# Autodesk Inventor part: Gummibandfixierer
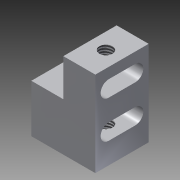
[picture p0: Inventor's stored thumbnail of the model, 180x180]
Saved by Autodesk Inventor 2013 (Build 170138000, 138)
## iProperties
Created: 2012-08
Part Number: Gummibandfixierer
Material: Aluminium 6061
Document SubType Name: Modeling
Designer: rYan
Mass: 2.85346 g
Surface Area: 11.8121 cm^2
Volume: 1.05294 cm^3
Density: 2.71 g/cm^3
Author: rYan
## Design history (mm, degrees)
sketch "Skizze1"
  geometry: L1 (0, 0)-(0, 16); L2 (0, 16)-(6, 16); L3 (6, 16)-(6, 9); L4 (6, 9)-(12, 9); L5 (12, 9)-(12, 0); L6 (12, 0)-(0, 0)
  constraints: 12 end point, 4 parallel, 1 perpendicular, 1 vertical
  dimensions: "d2" = 6 distance of L1.end L2.end; "d3" = 6 distance of L3.end L4.end; "d4" = 9 distance of L4.end L5.end; "d12" = 7 distance between parallel lines of L4 L2
extrude "Extrusion1" new body sketch "Skizze1" stored distance "d5" = 10; taper "d6" = 0 deg
sketch "Skizze2"
  geometry: L1 (9, 10)-(9, 0) reference; L2 (0, 10)-(0, 0) reference; L3 (4, 7.5)-(4, 2.5); L4 (7, 7.5)-(7, 2.5); L5 (0, 5)-(9, 5); A1 r 1.5 centre (5.5, 7.5) between (7, 7.5) and (4, 7.5); A2 r 1.5 centre (5.5, 2.5) between (4, 2.5) and (7, 2.5)
  constraints: 6 end point, 4 point on circle, 4 tangent, 2 centre point, 2 midpoint, 2 parallel, 1 symmetric about line
  dimensions: "d7" = 5 distance of A2.centre A1.centre; "d9" = 3 distance between parallel lines of L3 L4; "d38" = 2 distance between parallel lines of L1 L4
extrude "Extrusion2" cut sketch "Skizze2" stored distance "d10" = 10; taper "d11" = 0 deg
mirror "Spiegeln1"
sketch "Skizze3"
  geometry: L1 (6, 0)-(6, -10) reference; L2 (0, 0)-(6, 0) reference; L3 (0, 0)-(0, -10) reference; L4 (6, -10)-(0, -10) reference; L5 (6, -5)-(0, -5); L6 (3, 0)-(3, -10); 2 further points
  constraints: 5 midpoint, 4 end point
hole "Bohrung1" sketch "Skizze3" at (3, -5) diameter "d13" = 2.459; stored, may be unused: countersink angle "d17" = 90 deg, drill point angle "d19" = 118 deg; dims "d14" = 6, "d15" = 4, "d16" = 2, "d18" = 8
sketch "Skizze4"
  geometry: L1 (0, 0)-(6, 0) reference; L2 (0, 0)-(0, -10) reference; L3 (6, -10)-(0, -10) reference; L4 (3, 0)-(3, -10); L5 (6, -5)-(0, -5); 1 further point
  constraints: 4 end point, 4 midpoint
hole "Bohrung2" sketch "Skizze4" at (3, -5) diameter "d20" = 2.459; stored, may be unused: countersink angle "d24" = 90 deg, drill point angle "d26" = 118 deg; dims "d21" = 6, "d22" = 4, "d23" = 2, "d25" = 8
sketch "Skizze5"
  geometry: L1 (12, 0)-(12, -10) reference; L2 (0, -10)-(0, 0) reference; L3 (0, -5)-(12, -5); 2 further points
  constraints: 2 end point, 2 point on line, 1 midpoint
  dimensions: "d29" = 3 distance from line of L2 point (3, -5); "d30" = 6 distance of point (9, -5) point (3, -5)
hole "Bohrung3" sketch "Skizze5" at (3, -5), (9, -5) diameter "d31" = 2.459; stored, may be unused: countersink angle "d35" = 90 deg, drill point angle "d37" = 118 deg; dims "d32" = 3, "d33" = 4, "d34" = 2, "d36" = 3
node "Volumenkörper1"
